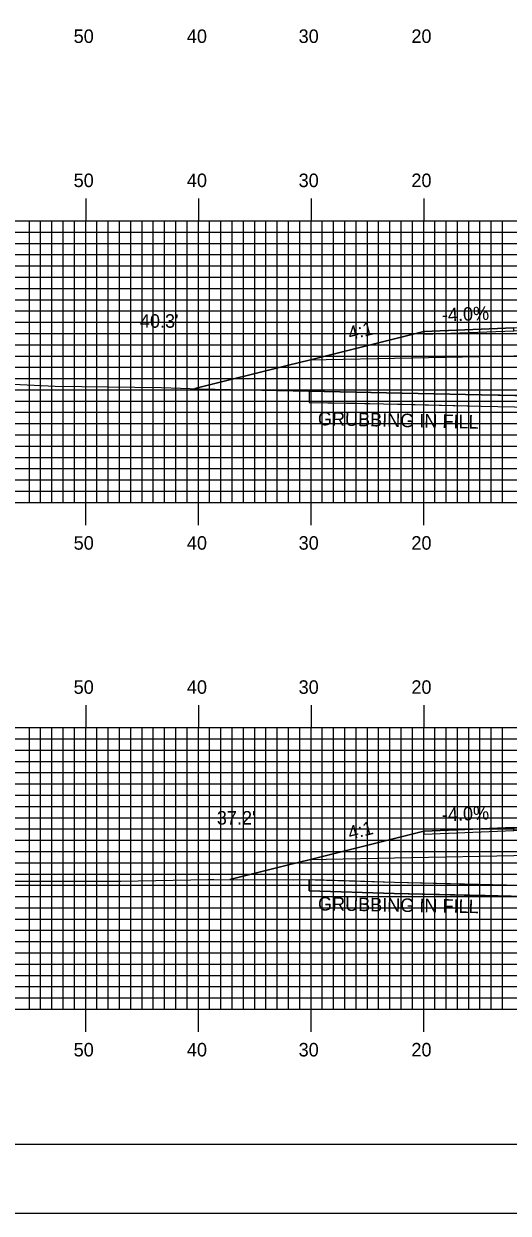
# Model space of a CAD drawing. Extents: x 1803897 to 1804240, y 442591 to 442811.
# Drawn here: x 1804007.2 to 1804050.2, y 442590.5 to 442696.2 of the extents above; entities that cross this region are included whole.
import ezdxf

# ---------------------------------------------------------------- set-up
doc = ezdxf.new("R2010")
doc.units = 0
for name, color, linetype in [('ANNOTATION', 7, 'Continuous'), ('BORDER', 7, 'Continuous'), ('D_Roadway_Centerline', 7, 'Continuous'), ('D_Roadway_Edge_Shoulder', 7, 'Continuous'), ('D_Roadway_SlopeLines', 7, 'Continuous'), ('D_Roadway_SubGrade', 7, 'Continuous'), ('D_Text_Standard', 7, 'Continuous'), ('GRUBBING IN FILL', 7, 'Continuous'), ('H_V ANNOTATION', 7, 'Continuous'), ('MAJOR', 7, 'Continuous'), ('MINOR', 7, 'Continuous'), ('PLOT BOUNDARY', 7, 'Continuous'), ('S_Roadway_Centerline', 7, 'Continuous')]:
    doc.layers.add(name, color=color, linetype=linetype)

msp = doc.modelspace()

# ---------------------------------------------------------------- linework, layer by layer
at = {"layer": 'BORDER'}
msp.add_lwpolyline([(1803913.05, 442596.67), (1804233.05, 442596.67), (1804233.05, 442806.67), (1803913.05, 442806.67)], close=True, dxfattribs=at)
at = {"layer": 'D_Roadway_Centerline'}
for points in [[(1804022.33, 442663.77), (1804030.65, 442665.85), (1804032.48, 442666.3), (1804042.65, 442668.85), (1804050.65, 442669.17), (1804062.65, 442669.46), (1804074.65, 442669.74), (1804082.65, 442669.42), (1804092.83, 442666.88), (1804112.93, 442661.85)], [(1804025.43, 442620.17), (1804030.65, 442621.47), (1804032.48, 442621.93), (1804042.65, 442624.47), (1804050.65, 442624.79), (1804062.65, 442625.08), (1804074.65, 442625.37), (1804082.65, 442625.05), (1804092.83, 442622.51), (1804108.23, 442618.66)]]:
    msp.add_lwpolyline(points, dxfattribs=at)
at = {"layer": 'D_Roadway_Edge_Shoulder'}
for points in [[(1804050.65, 442669.17), (1804042.65, 442668.85), (1804042.65, 442668.6), (1804050.65, 442668.92)], [(1804050.65, 442624.79), (1804042.65, 442624.47), (1804042.65, 442624.22), (1804050.65, 442624.54)]]:
    msp.add_lwpolyline(points, close=True, dxfattribs=at)
at = {"layer": 'D_Roadway_SlopeLines'}
for points in [[(1804042.65, 442668.85), (1804032.48, 442666.3), (1804030.65, 442665.85), (1804022.33, 442663.77)], [(1804042.65, 442624.47), (1804032.48, 442621.93), (1804030.65, 442621.47), (1804025.43, 442620.17)]]:
    msp.add_lwpolyline(points, dxfattribs=at)
at = {"layer": 'D_Roadway_SubGrade'}
for points in [[(1804050.65, 442666.67), (1804032.48, 442666.3), (1804042.65, 442668.85), (1804042.65, 442668.6), (1804050.65, 442668.92), (1804062.65, 442669.21), (1804074.65, 442669.49), (1804082.65, 442669.17), (1804082.65, 442669.42), (1804092.83, 442666.88), (1804074.65, 442667.24), (1804062.65, 442666.96)], [(1804050.65, 442622.29), (1804032.48, 442621.93), (1804042.65, 442624.47), (1804042.65, 442624.22), (1804050.65, 442624.54), (1804062.65, 442624.83), (1804074.65, 442625.12), (1804082.65, 442624.8), (1804082.65, 442625.05), (1804092.83, 442622.51), (1804074.65, 442622.87), (1804062.65, 442622.58)]]:
    msp.add_lwpolyline(points, close=True, dxfattribs=at)
at = {"layer": 'GRUBBING IN FILL'}
for p, q in [((1804032.48, 442663.55), (1804032.48, 442662.55)), ((1804032.48, 442663.55), (1804032.48, 442662.55)), ((1804032.48, 442620.19), (1804032.48, 442619.18)), ((1804032.48, 442620.19), (1804032.48, 442619.18))]:
    msp.add_line(p, q, dxfattribs=at)
for points in [[(1804032.48, 442663.55), (1804032.48, 442662.55), (1804036.61, 442662.47), (1804047.76, 442662.22), (1804061.06, 442661.96), (1804062.65, 442661.95), (1804062.65, 442662.95), (1804061.07, 442662.96), (1804054.42, 442663.09), (1804047.78, 442663.22), (1804040.75, 442663.38)], [(1804032.48, 442663.55), (1804032.48, 442662.55), (1804036.61, 442662.47), (1804047.76, 442662.22), (1804061.06, 442661.96), (1804062.65, 442661.95), (1804062.65, 442662.95), (1804061.07, 442662.96), (1804054.42, 442663.09), (1804047.78, 442663.22), (1804040.75, 442663.38)], [(1804032.48, 442620.19), (1804033.83, 442620.14), (1804036.53, 442620.05), (1804040.05, 442619.94), (1804048.14, 442619.75), (1804056.23, 442619.56), (1804059.61, 442619.47), (1804062.65, 442619.43), (1804062.65, 442618.43), (1804059.58, 442618.47), (1804056.21, 442618.56), (1804048.12, 442618.75), (1804040.02, 442618.94), (1804032.48, 442619.18)], [(1804032.48, 442620.19), (1804033.83, 442620.14), (1804036.53, 442620.05), (1804040.05, 442619.94), (1804048.14, 442619.75), (1804056.23, 442619.56), (1804059.61, 442619.47), (1804062.65, 442619.43), (1804062.65, 442618.43), (1804059.58, 442618.47), (1804056.21, 442618.56), (1804048.12, 442618.75), (1804040.02, 442618.94), (1804032.48, 442619.18)]]:
    msp.add_lwpolyline(points, close=True, dxfattribs=at)
for points in [[(1804032.48, 442662.55), (1804040.73, 442662.38), (1804047.76, 442662.22), (1804061.06, 442661.96), (1804072.57, 442661.85), (1804083.24, 442661.52), (1804092.83, 442661.33)], [(1804032.48, 442662.55), (1804040.73, 442662.38), (1804047.76, 442662.22), (1804061.06, 442661.96), (1804072.57, 442661.85), (1804083.24, 442661.52), (1804092.83, 442661.33)], [(1804032.48, 442619.18), (1804040.02, 442618.94), (1804056.21, 442618.56), (1804058.07, 442618.53), (1804059.58, 442618.47), (1804079.36, 442618.17), (1804081.03, 442618.17), (1804082.61, 442618.17), (1804092.83, 442617.93)], [(1804032.48, 442619.18), (1804040.02, 442618.94), (1804056.21, 442618.56), (1804058.07, 442618.53), (1804059.58, 442618.47), (1804079.36, 442618.17), (1804081.03, 442618.17), (1804082.61, 442618.17), (1804092.83, 442617.93)]]:
    msp.add_lwpolyline(points, dxfattribs=at)
at = {"layer": 'MAJOR'}
for p, q in [((1804012.65, 442680.67), (1804012.65, 442678.67)), ((1804022.65, 442680.67), (1804022.65, 442678.67)), ((1804032.65, 442680.67), (1804032.65, 442678.67)), ((1804042.65, 442680.67), (1804042.65, 442678.67)), ((1803922.65, 442678.67), (1804202.65, 442678.67)), ((1803922.65, 442678.67), (1804202.65, 442678.67)), ((1804012.65, 442653.67), (1804012.65, 442678.67)), ((1804022.65, 442653.67), (1804022.65, 442678.67)), ((1804032.65, 442653.67), (1804032.65, 442678.67)), ((1804042.65, 442653.67), (1804042.65, 442678.67)), ((1803922.65, 442673.67), (1804202.65, 442673.67)), ((1803922.65, 442668.67), (1804202.65, 442668.67)), ((1803922.65, 442663.67), (1804202.65, 442663.67)), ((1803922.65, 442658.67), (1804202.65, 442658.67)), ((1803922.65, 442653.67), (1804202.65, 442653.67)), ((1803922.65, 442653.67), (1804202.65, 442653.67)), ((1804012.65, 442651.66), (1804012.65, 442653.67)), ((1804022.65, 442651.66), (1804022.65, 442653.67)), ((1804032.65, 442651.66), (1804032.65, 442653.67)), ((1804042.65, 442651.66), (1804042.65, 442653.67)), ((1804012.65, 442635.67), (1804012.65, 442633.67)), ((1804022.65, 442635.67), (1804022.65, 442633.67)), ((1804032.65, 442635.67), (1804032.65, 442633.67)), ((1804042.65, 442635.67), (1804042.65, 442633.67)), ((1803922.65, 442633.67), (1804202.65, 442633.67)), ((1803922.65, 442633.67), (1804202.65, 442633.67)), ((1804012.65, 442608.67), (1804012.65, 442633.67)), ((1804022.65, 442608.67), (1804022.65, 442633.67)), ((1804032.65, 442608.67), (1804032.65, 442633.67)), ((1804042.65, 442608.67), (1804042.65, 442633.67)), ((1803922.65, 442628.67), (1804202.65, 442628.67)), ((1803922.65, 442623.67), (1804202.65, 442623.67)), ((1803922.65, 442618.67), (1804202.65, 442618.67)), ((1803922.65, 442613.67), (1804202.65, 442613.67)), ((1803922.65, 442608.67), (1804202.65, 442608.67)), ((1803922.65, 442608.67), (1804202.65, 442608.67)), ((1804012.65, 442606.66), (1804012.65, 442608.67)), ((1804022.65, 442606.66), (1804022.65, 442608.67)), ((1804032.65, 442606.66), (1804032.65, 442608.67)), ((1804042.65, 442606.66), (1804042.65, 442608.67))]:
    msp.add_line(p, q, dxfattribs=at)
at = {"layer": 'MINOR'}
for p, q in [((1804007.65, 442653.67), (1804007.65, 442678.67)), ((1804008.65, 442653.67), (1804008.65, 442678.67)), ((1804009.65, 442653.67), (1804009.65, 442678.67)), ((1804010.65, 442653.67), (1804010.65, 442678.67)), ((1804011.65, 442653.67), (1804011.65, 442678.67)), ((1804013.65, 442653.67), (1804013.65, 442678.67)), ((1804014.65, 442653.67), (1804014.65, 442678.67)), ((1804015.65, 442653.67), (1804015.65, 442678.67)), ((1804016.65, 442653.67), (1804016.65, 442678.67)), ((1804017.65, 442653.67), (1804017.65, 442678.67)), ((1804018.65, 442653.67), (1804018.65, 442678.67)), ((1804019.65, 442653.67), (1804019.65, 442678.67)), ((1804020.65, 442653.67), (1804020.65, 442678.67)), ((1804021.65, 442653.67), (1804021.65, 442678.67)), ((1804023.65, 442653.67), (1804023.65, 442678.67)), ((1804024.65, 442653.67), (1804024.65, 442678.67)), ((1804025.65, 442653.67), (1804025.65, 442678.67)), ((1804026.65, 442653.67), (1804026.65, 442678.67)), ((1804027.65, 442653.67), (1804027.65, 442678.67)), ((1804028.65, 442653.67), (1804028.65, 442678.67)), ((1804029.65, 442653.67), (1804029.65, 442678.67)), ((1804030.65, 442653.67), (1804030.65, 442678.67)), ((1804031.65, 442653.67), (1804031.65, 442678.67)), ((1804033.65, 442653.67), (1804033.65, 442678.67)), ((1804034.65, 442653.67), (1804034.65, 442678.67)), ((1804035.65, 442653.67), (1804035.65, 442678.67)), ((1804036.65, 442653.67), (1804036.65, 442678.67)), ((1804037.65, 442653.67), (1804037.65, 442678.67)), ((1804038.65, 442653.67), (1804038.65, 442678.67)), ((1804039.65, 442653.67), (1804039.65, 442678.67)), ((1804040.65, 442653.67), (1804040.65, 442678.67)), ((1804041.65, 442653.67), (1804041.65, 442678.67)), ((1804043.65, 442653.67), (1804043.65, 442678.67)), ((1804044.65, 442653.67), (1804044.65, 442678.67)), ((1804045.65, 442653.67), (1804045.65, 442678.67)), ((1804046.65, 442653.67), (1804046.65, 442678.67)), ((1804047.65, 442653.67), (1804047.65, 442678.67)), ((1804048.65, 442653.67), (1804048.65, 442678.67)), ((1804049.65, 442653.67), (1804049.65, 442678.67)), ((1803922.65, 442677.67), (1804202.65, 442677.67)), ((1803922.65, 442676.67), (1804202.65, 442676.67)), ((1803922.65, 442675.67), (1804202.65, 442675.67)), ((1803922.65, 442674.67), (1804202.65, 442674.67)), ((1803922.65, 442672.67), (1804202.65, 442672.67)), ((1803922.65, 442671.67), (1804202.65, 442671.67)), ((1803922.65, 442670.67), (1804202.65, 442670.67)), ((1803922.65, 442669.67), (1804202.65, 442669.67)), ((1803922.65, 442667.67), (1804202.65, 442667.67)), ((1803922.65, 442666.67), (1804202.65, 442666.67)), ((1803922.65, 442665.67), (1804202.65, 442665.67)), ((1803922.65, 442664.67), (1804202.65, 442664.67)), ((1803922.65, 442662.67), (1804202.65, 442662.67)), ((1803922.65, 442661.67), (1804202.65, 442661.67)), ((1803922.65, 442660.67), (1804202.65, 442660.67)), ((1803922.65, 442659.67), (1804202.65, 442659.67)), ((1803922.65, 442657.67), (1804202.65, 442657.67)), ((1803922.65, 442656.67), (1804202.65, 442656.67)), ((1803922.65, 442655.67), (1804202.65, 442655.67)), ((1803922.65, 442654.67), (1804202.65, 442654.67)), ((1804007.65, 442608.67), (1804007.65, 442633.67)), ((1804008.65, 442608.67), (1804008.65, 442633.67)), ((1804009.65, 442608.67), (1804009.65, 442633.67)), ((1804010.65, 442608.67), (1804010.65, 442633.67)), ((1804011.65, 442608.67), (1804011.65, 442633.67)), ((1804013.65, 442608.67), (1804013.65, 442633.67)), ((1804014.65, 442608.67), (1804014.65, 442633.67)), ((1804015.65, 442608.67), (1804015.65, 442633.67)), ((1804016.65, 442608.67), (1804016.65, 442633.67)), ((1804017.65, 442608.67), (1804017.65, 442633.67)), ((1804018.65, 442608.67), (1804018.65, 442633.67)), ((1804019.65, 442608.67), (1804019.65, 442633.67)), ((1804020.65, 442608.67), (1804020.65, 442633.67)), ((1804021.65, 442608.67), (1804021.65, 442633.67)), ((1804023.65, 442608.67), (1804023.65, 442633.67)), ((1804024.65, 442608.67), (1804024.65, 442633.67)), ((1804025.65, 442608.67), (1804025.65, 442633.67)), ((1804026.65, 442608.67), (1804026.65, 442633.67)), ((1804027.65, 442608.67), (1804027.65, 442633.67)), ((1804028.65, 442608.67), (1804028.65, 442633.67)), ((1804029.65, 442608.67), (1804029.65, 442633.67)), ((1804030.65, 442608.67), (1804030.65, 442633.67)), ((1804031.65, 442608.67), (1804031.65, 442633.67)), ((1804033.65, 442608.67), (1804033.65, 442633.67)), ((1804034.65, 442608.67), (1804034.65, 442633.67)), ((1804035.65, 442608.67), (1804035.65, 442633.67)), ((1804036.65, 442608.67), (1804036.65, 442633.67)), ((1804037.65, 442608.67), (1804037.65, 442633.67)), ((1804038.65, 442608.67), (1804038.65, 442633.67)), ((1804039.65, 442608.67), (1804039.65, 442633.67)), ((1804040.65, 442608.67), (1804040.65, 442633.67)), ((1804041.65, 442608.67), (1804041.65, 442633.67)), ((1804043.65, 442608.67), (1804043.65, 442633.67)), ((1804044.65, 442608.67), (1804044.65, 442633.67)), ((1804045.65, 442608.67), (1804045.65, 442633.67)), ((1804046.65, 442608.67), (1804046.65, 442633.67)), ((1804047.65, 442608.67), (1804047.65, 442633.67)), ((1804048.65, 442608.67), (1804048.65, 442633.67)), ((1804049.65, 442608.67), (1804049.65, 442633.67)), ((1803922.65, 442632.67), (1804202.65, 442632.67)), ((1803922.65, 442631.67), (1804202.65, 442631.67)), ((1803922.65, 442630.67), (1804202.65, 442630.67)), ((1803922.65, 442629.67), (1804202.65, 442629.67)), ((1803922.65, 442627.67), (1804202.65, 442627.67)), ((1803922.65, 442626.67), (1804202.65, 442626.67)), ((1803922.65, 442625.67), (1804202.65, 442625.67)), ((1803922.65, 442624.67), (1804202.65, 442624.67)), ((1803922.65, 442622.67), (1804202.65, 442622.67)), ((1803922.65, 442621.67), (1804202.65, 442621.67)), ((1803922.65, 442620.67), (1804202.65, 442620.67)), ((1803922.65, 442619.67), (1804202.65, 442619.67)), ((1803922.65, 442617.67), (1804202.65, 442617.67)), ((1803922.65, 442616.67), (1804202.65, 442616.67)), ((1803922.65, 442615.67), (1804202.65, 442615.67)), ((1803922.65, 442614.67), (1804202.65, 442614.67)), ((1803922.65, 442612.67), (1804202.65, 442612.67)), ((1803922.65, 442611.67), (1804202.65, 442611.67)), ((1803922.65, 442610.67), (1804202.65, 442610.67)), ((1803922.65, 442609.67), (1804202.65, 442609.67))]:
    msp.add_line(p, q, dxfattribs=at)
at = {"layer": 'PLOT BOUNDARY'}
msp.add_lwpolyline([(1803896.87, 442590.55), (1804236.87, 442590.55), (1804236.87, 442810.55), (1803896.87, 442810.55)], close=True, dxfattribs=at)
at = {"layer": 'S_Roadway_Centerline'}
for points in [[(1804005.59, 442664.19), (1804009.95, 442663.99), (1804019.39, 442663.87), (1804022.75, 442663.75), (1804040.75, 442663.38), (1804047.78, 442663.22), (1804061.07, 442662.96), (1804072.59, 442662.85), (1804083.27, 442662.52), (1804096.71, 442662.26), (1804104.76, 442662.06), (1804112.68, 442661.87), (1804121.32, 442661.47)], [(1804004.74, 442620.03), (1804015.78, 442620.02), (1804023.52, 442620.17), (1804023.56, 442620.17), (1804024.03, 442620.17), (1804031.08, 442620.16), (1804032.81, 442620.19), (1804033.02, 442620.16), (1804040.05, 442619.94), (1804056.23, 442619.56), (1804058.1, 442619.53), (1804059.61, 442619.47), (1804079.37, 442619.17), (1804081.03, 442619.17), (1804082.62, 442619.17), (1804093.2, 442618.92), (1804104.33, 442618.78), (1804104.72, 442618.78), (1804117.17, 442618.34), (1804126.83, 442618)]]:
    msp.add_lwpolyline(points, dxfattribs=at)

# ---------------------------------------------------------------- texts
at = {"layer": 'ANNOTATION'}
for s, rotation, p in [('-4.0%', 2.2906, (1804044.29, 442669.72)), ('4:1', 14.0362, (1804036.1, 442668.07)), ('-4.0%', 2.2906, (1804044.29, 442625.34)), ('4:1', 14.0362, (1804036.1, 442623.7))]:
    msp.add_text(s, height=1.2, rotation=rotation, dxfattribs=at).set_placement(p)
at = {"layer": 'D_Text_Standard'}
for s, p in [("40.3'", (1804017.46, 442669.18)), ("37.2'", (1804024.29, 442625.06))]:
    msp.add_text(s, height=1.2, dxfattribs=at).set_placement(p)
at = {"layer": 'GRUBBING IN FILL'}
for rotation, p in [(358.7682, (1804033.25, 442660.52)), (358.9887, (1804033.26, 442617.44))]:
    msp.add_text('GRUBBING IN FILL', height=1.2, rotation=rotation, dxfattribs=at).set_placement(p)
at = {"layer": 'H_V ANNOTATION'}
for s, p in [('50', (1804011.58, 442694.47)), ('40', (1804021.63, 442694.47)), ('30', (1804031.55, 442694.47)), ('20', (1804041.56, 442694.47)), ('50', (1804011.58, 442681.67)), ('40', (1804021.63, 442681.67)), ('30', (1804031.55, 442681.67)), ('20', (1804041.56, 442681.67)), ('50', (1804011.58, 442649.47)), ('40', (1804021.63, 442649.47)), ('30', (1804031.55, 442649.47)), ('20', (1804041.56, 442649.47)), ('50', (1804011.58, 442636.67)), ('40', (1804021.63, 442636.67)), ('30', (1804031.55, 442636.67)), ('20', (1804041.56, 442636.67)), ('50', (1804011.58, 442604.47)), ('40', (1804021.63, 442604.47)), ('30', (1804031.55, 442604.47)), ('20', (1804041.56, 442604.47))]:
    msp.add_text(s, height=1.2, dxfattribs=at).set_placement(p)

doc.saveas('drawing.dxf')
